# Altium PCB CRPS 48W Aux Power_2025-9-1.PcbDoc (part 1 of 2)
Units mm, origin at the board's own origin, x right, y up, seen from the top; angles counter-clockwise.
Board outline 50 x 33.8 mm, 6 copper layers (TopLayer, Layer2, Layer3, Layer4, Layer5, BottomLayer), stack 1.394 mm thick; 52 components, 33 nets, 144 pads, 115 vias.
Unrouted connection lines stored in the file: 30.
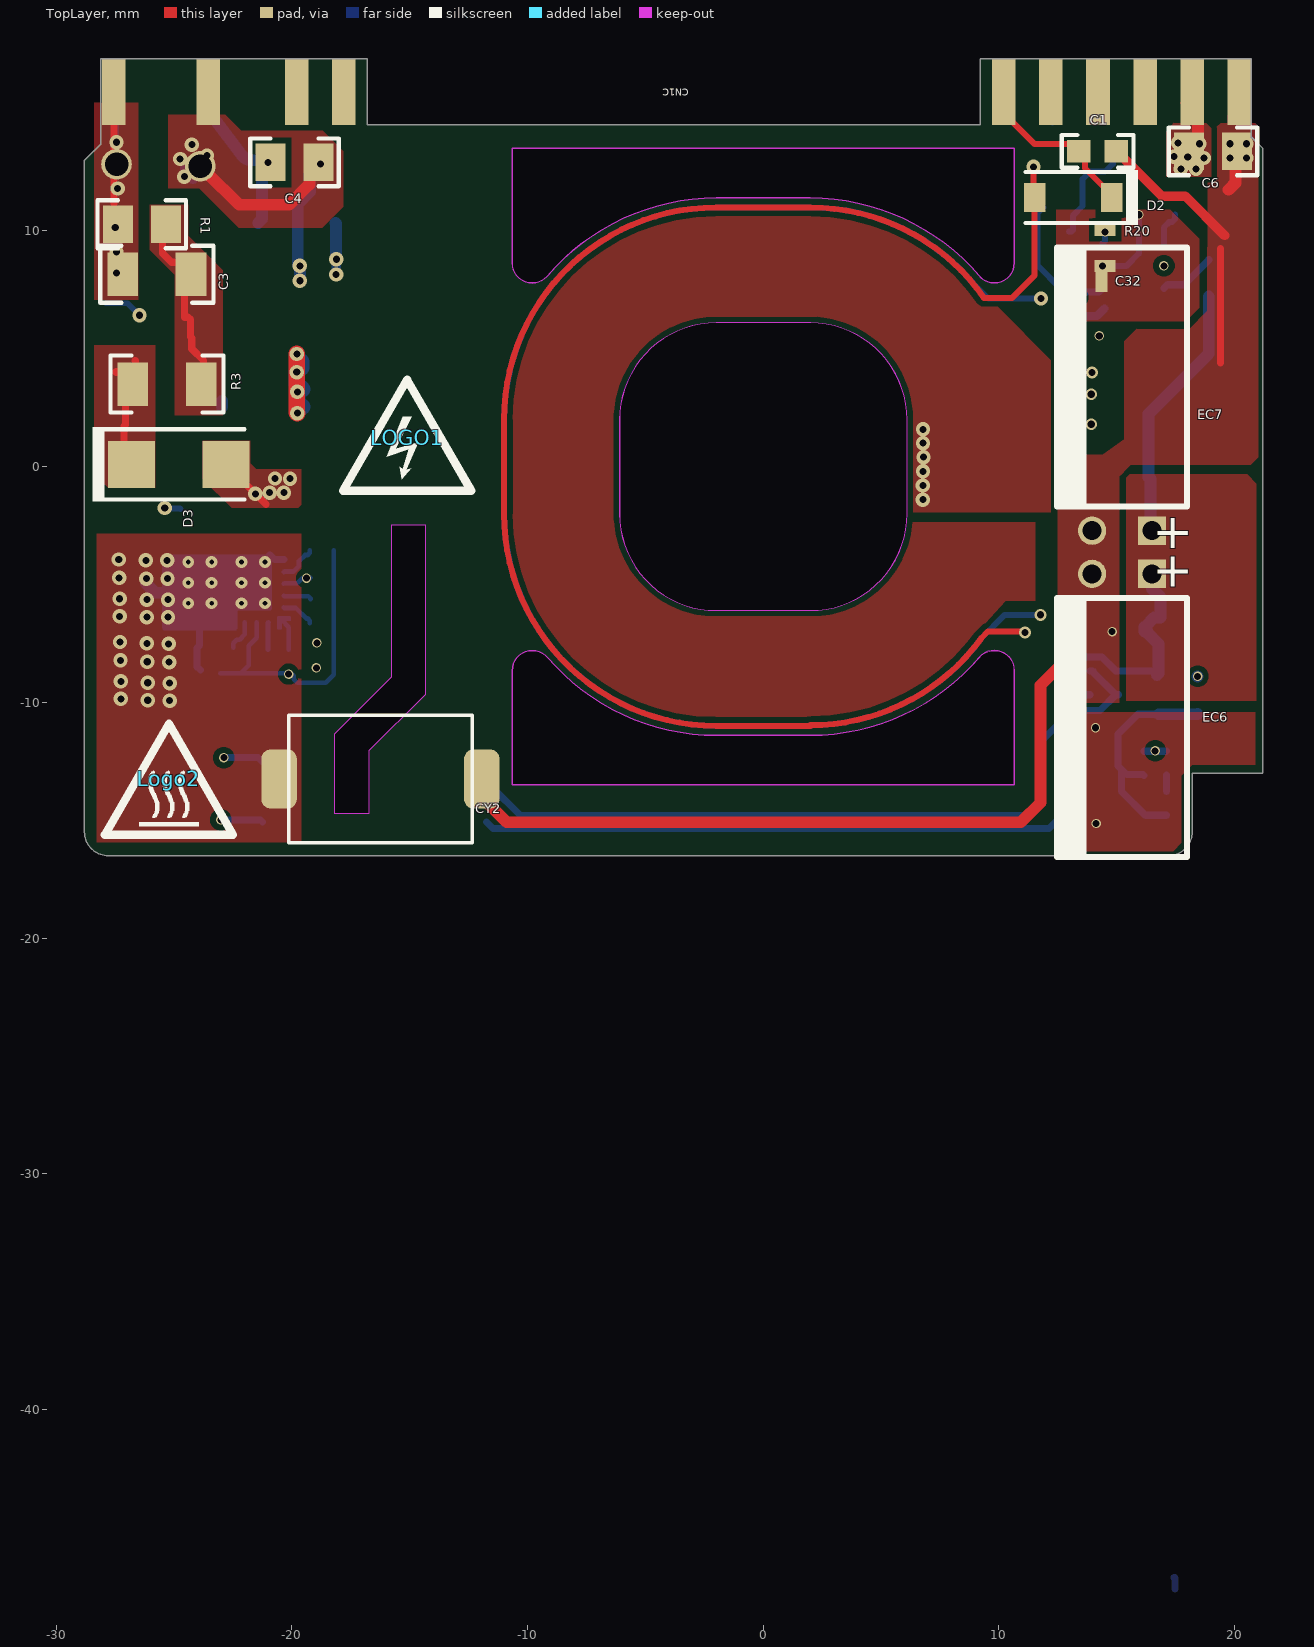
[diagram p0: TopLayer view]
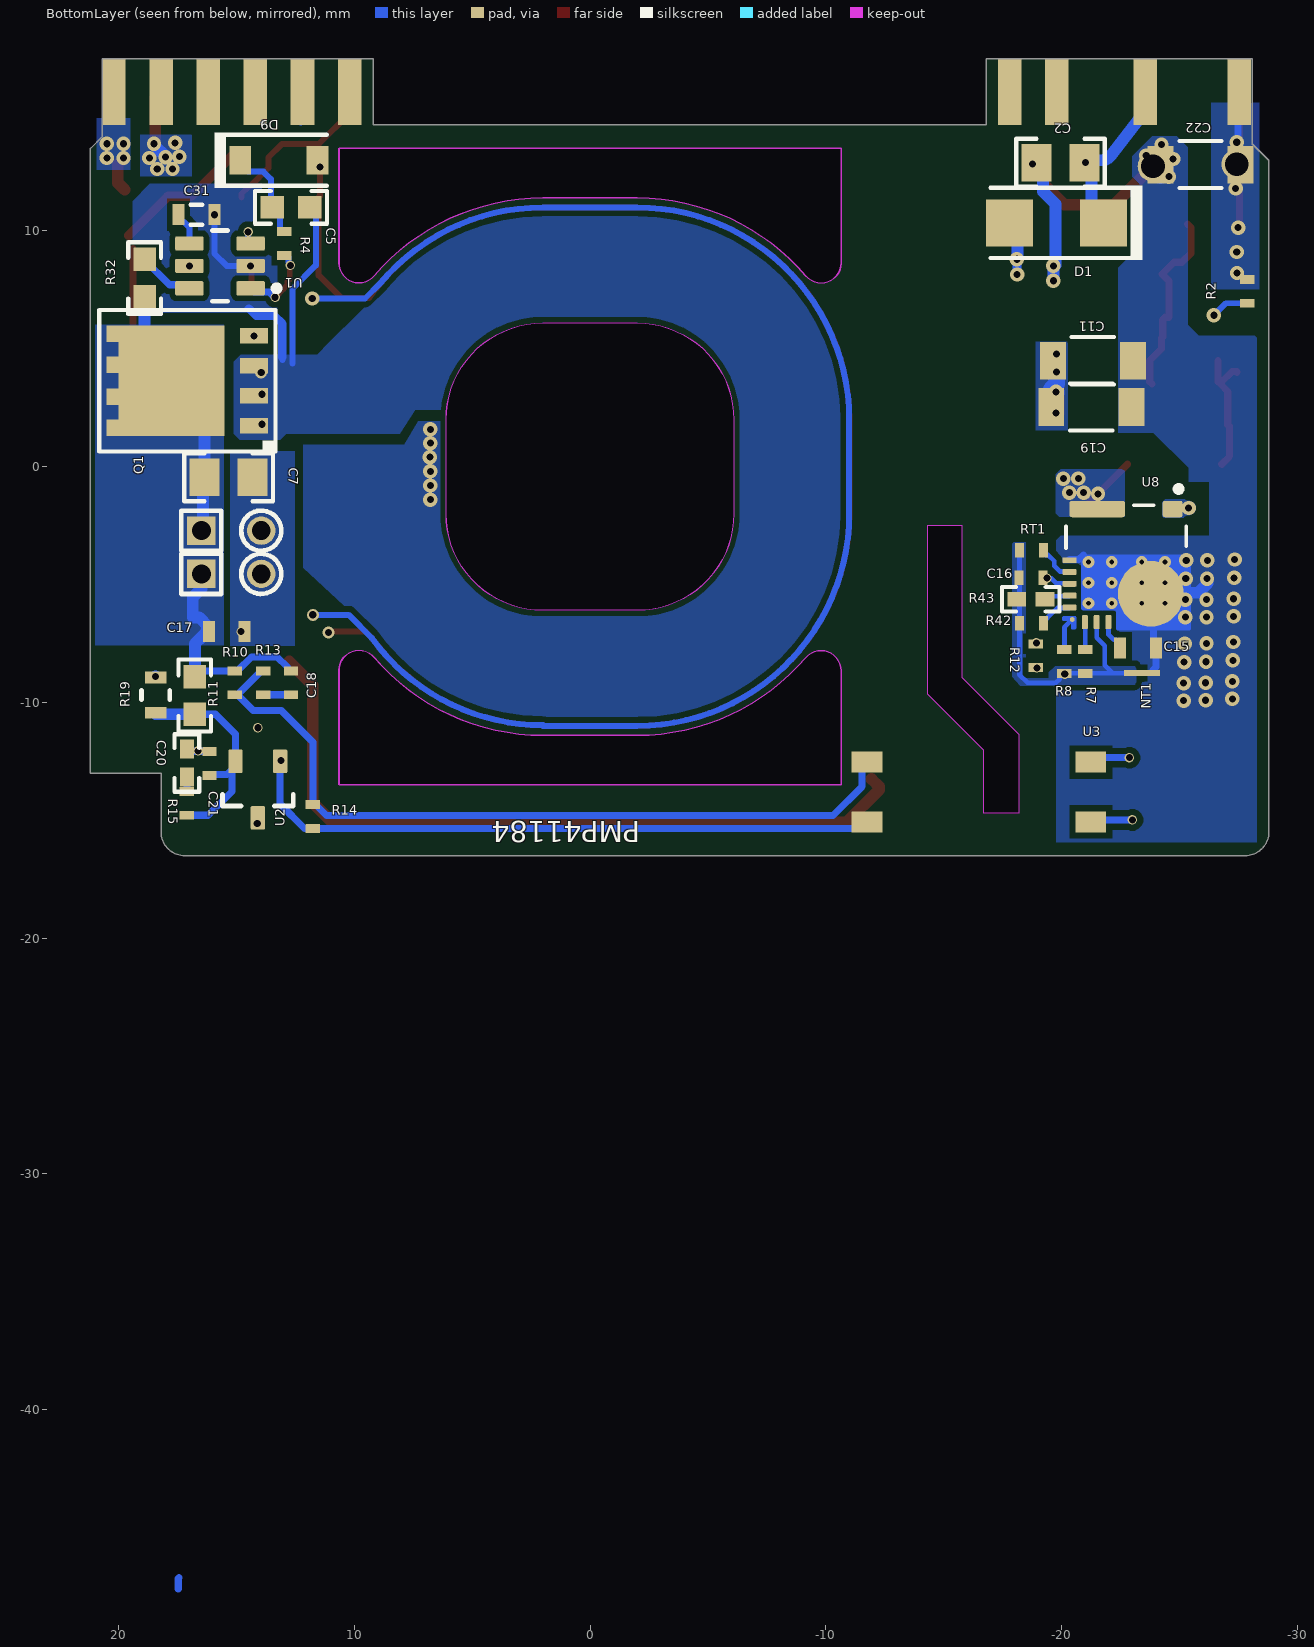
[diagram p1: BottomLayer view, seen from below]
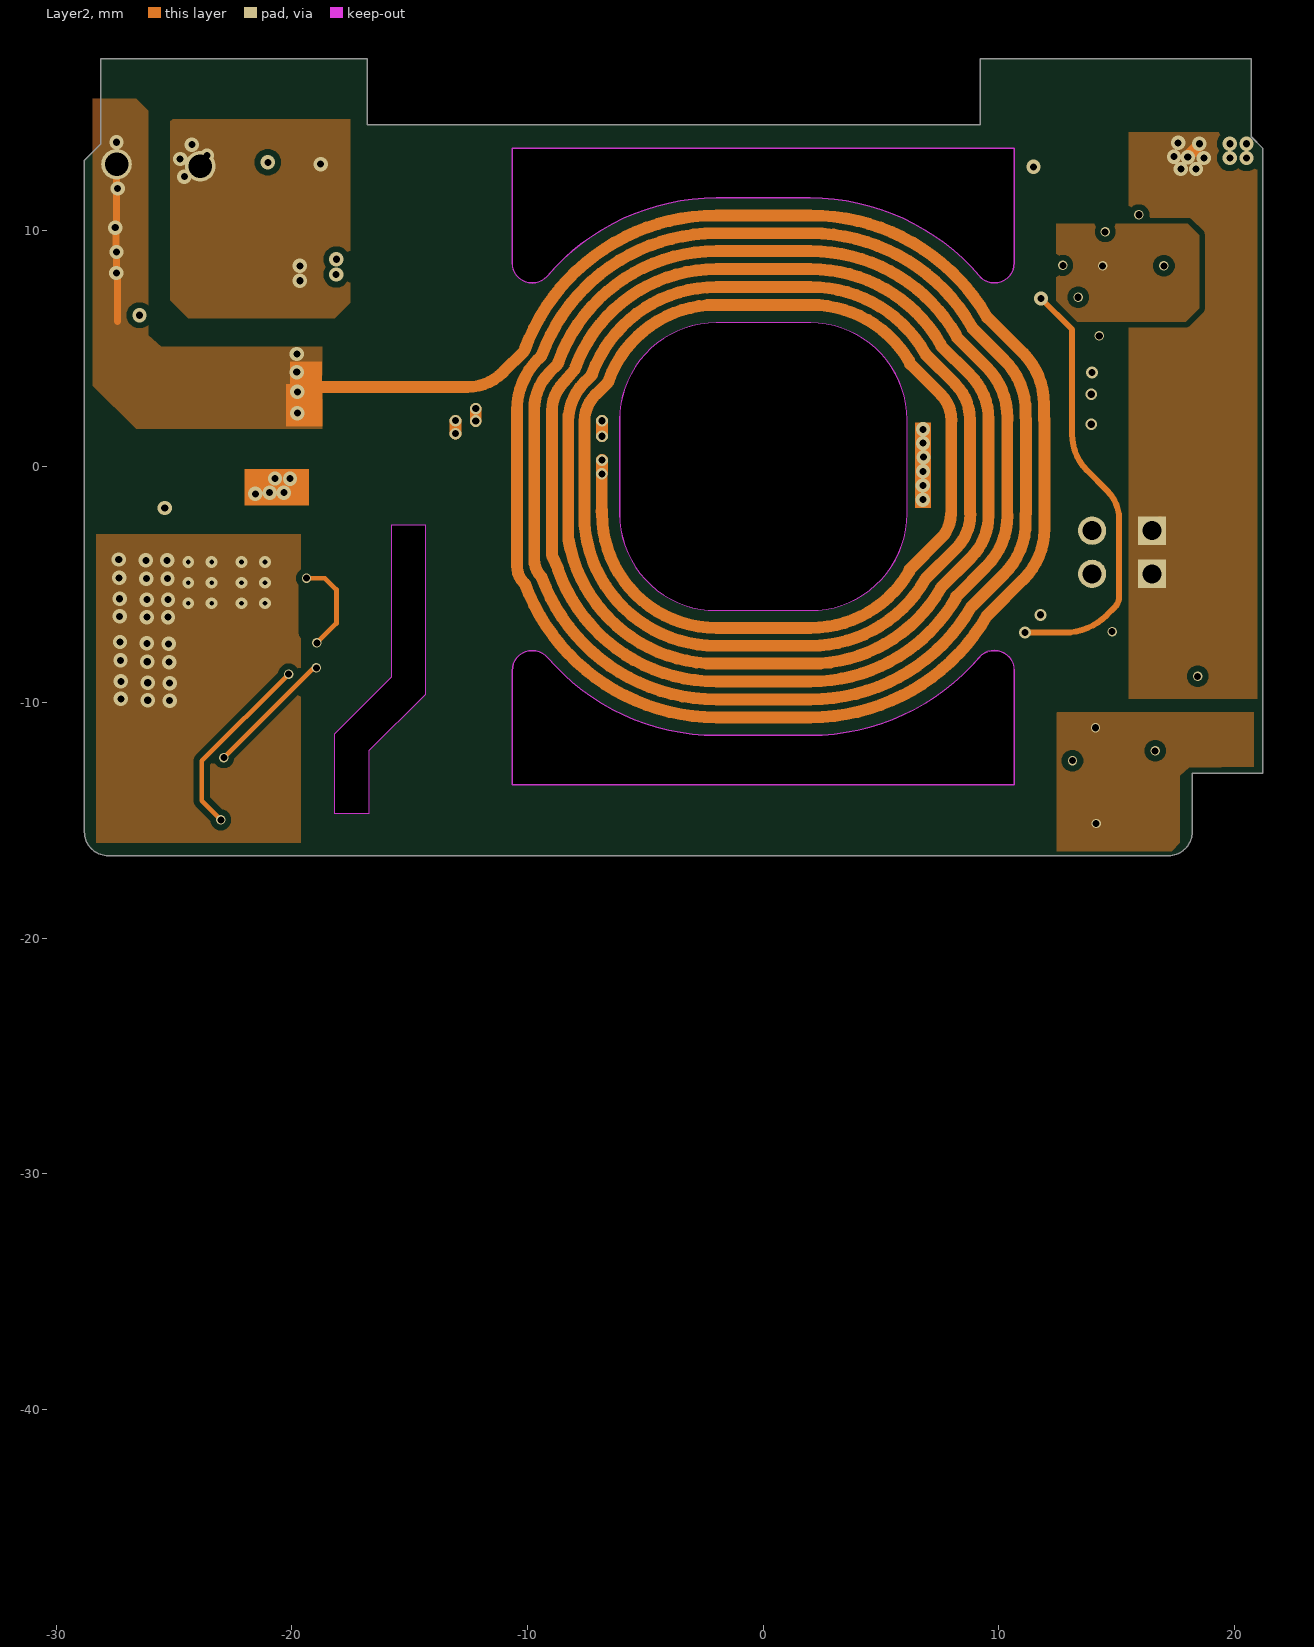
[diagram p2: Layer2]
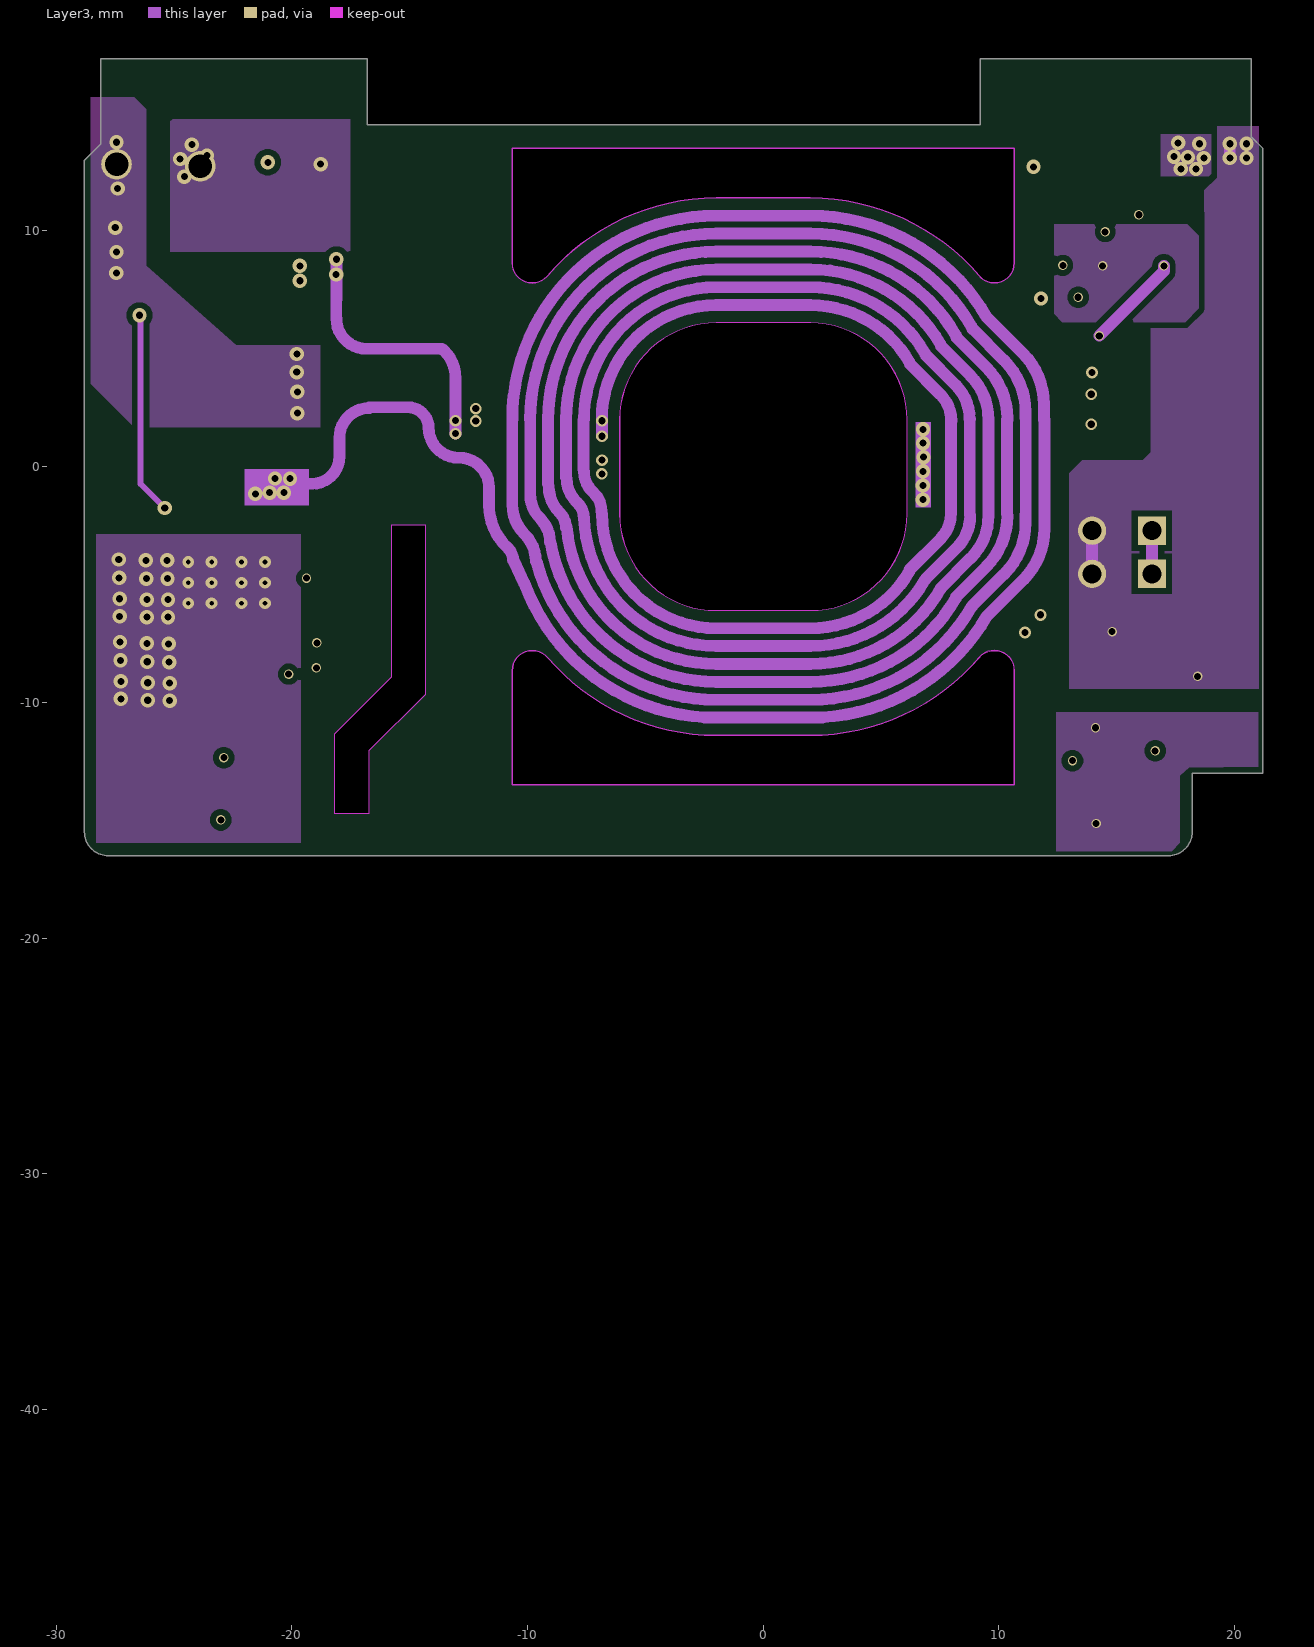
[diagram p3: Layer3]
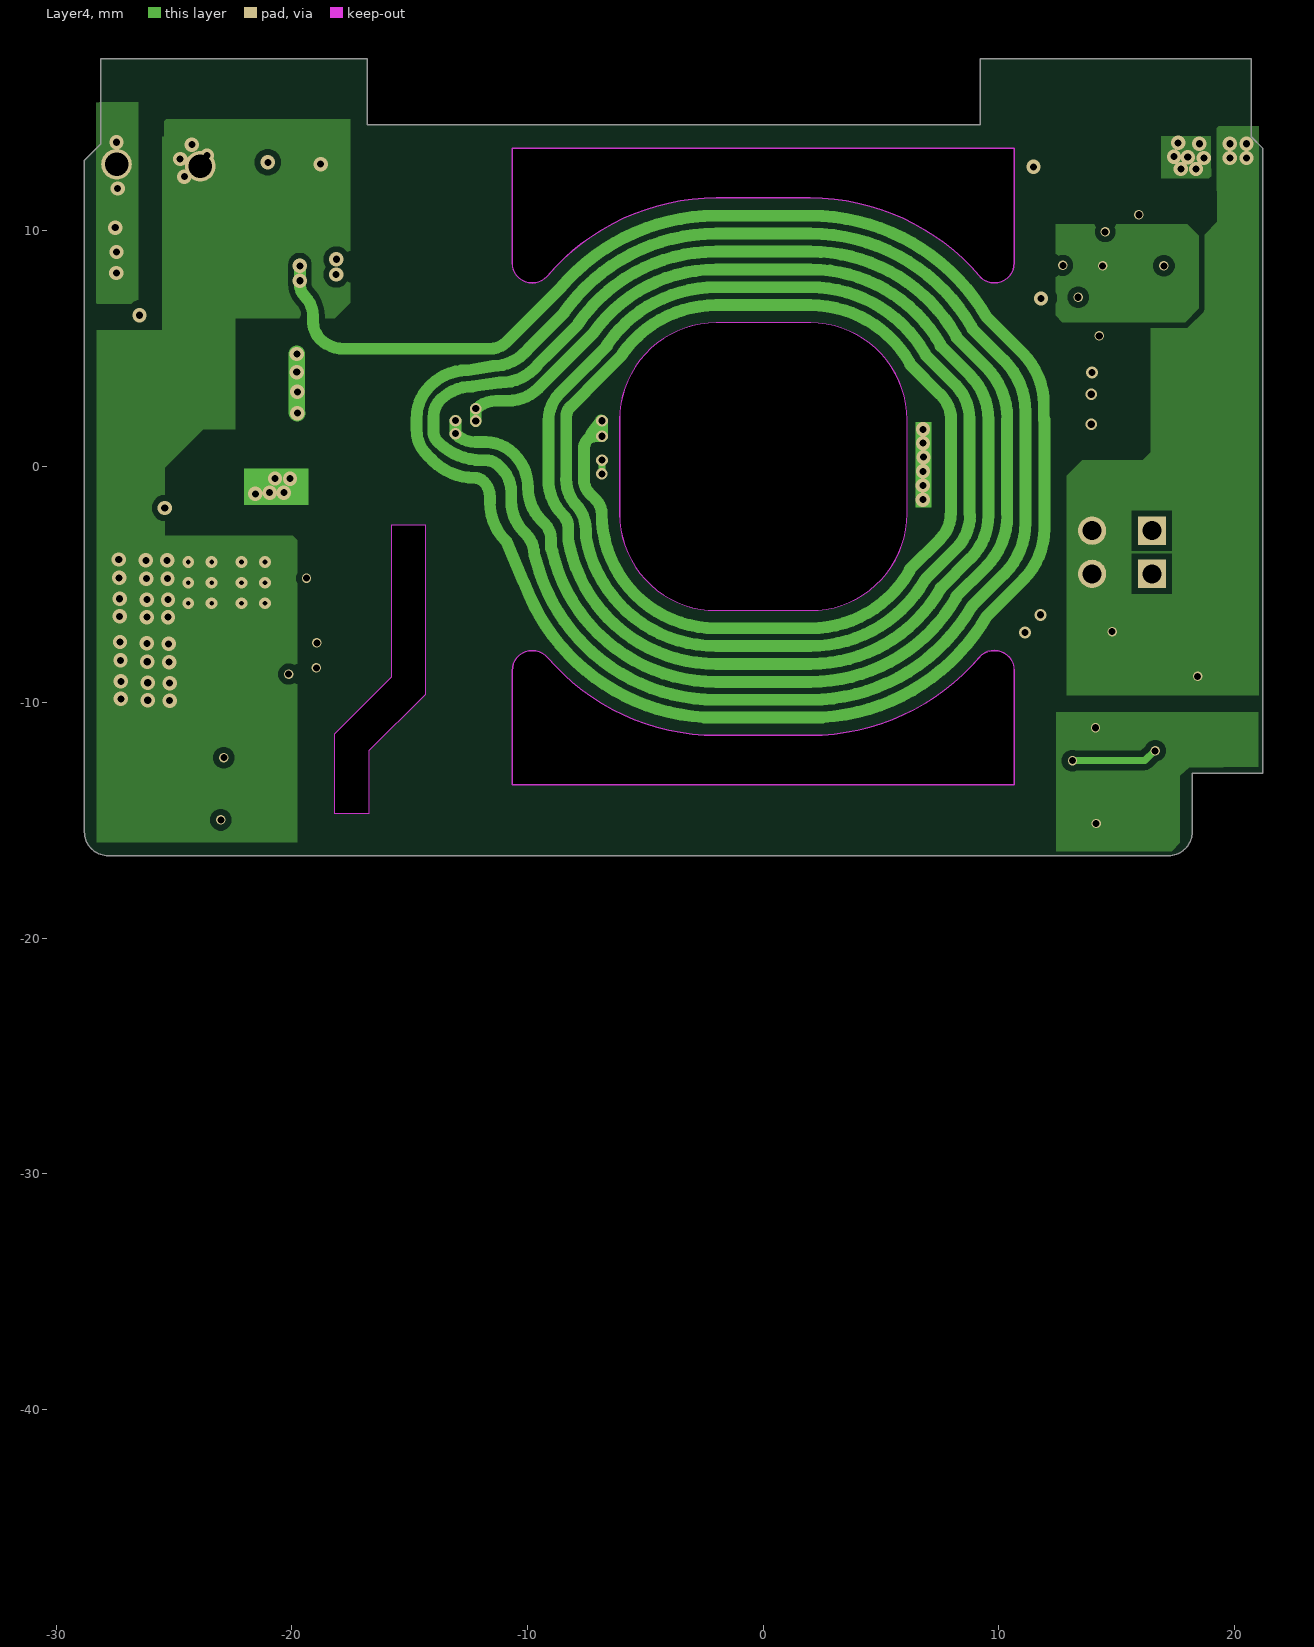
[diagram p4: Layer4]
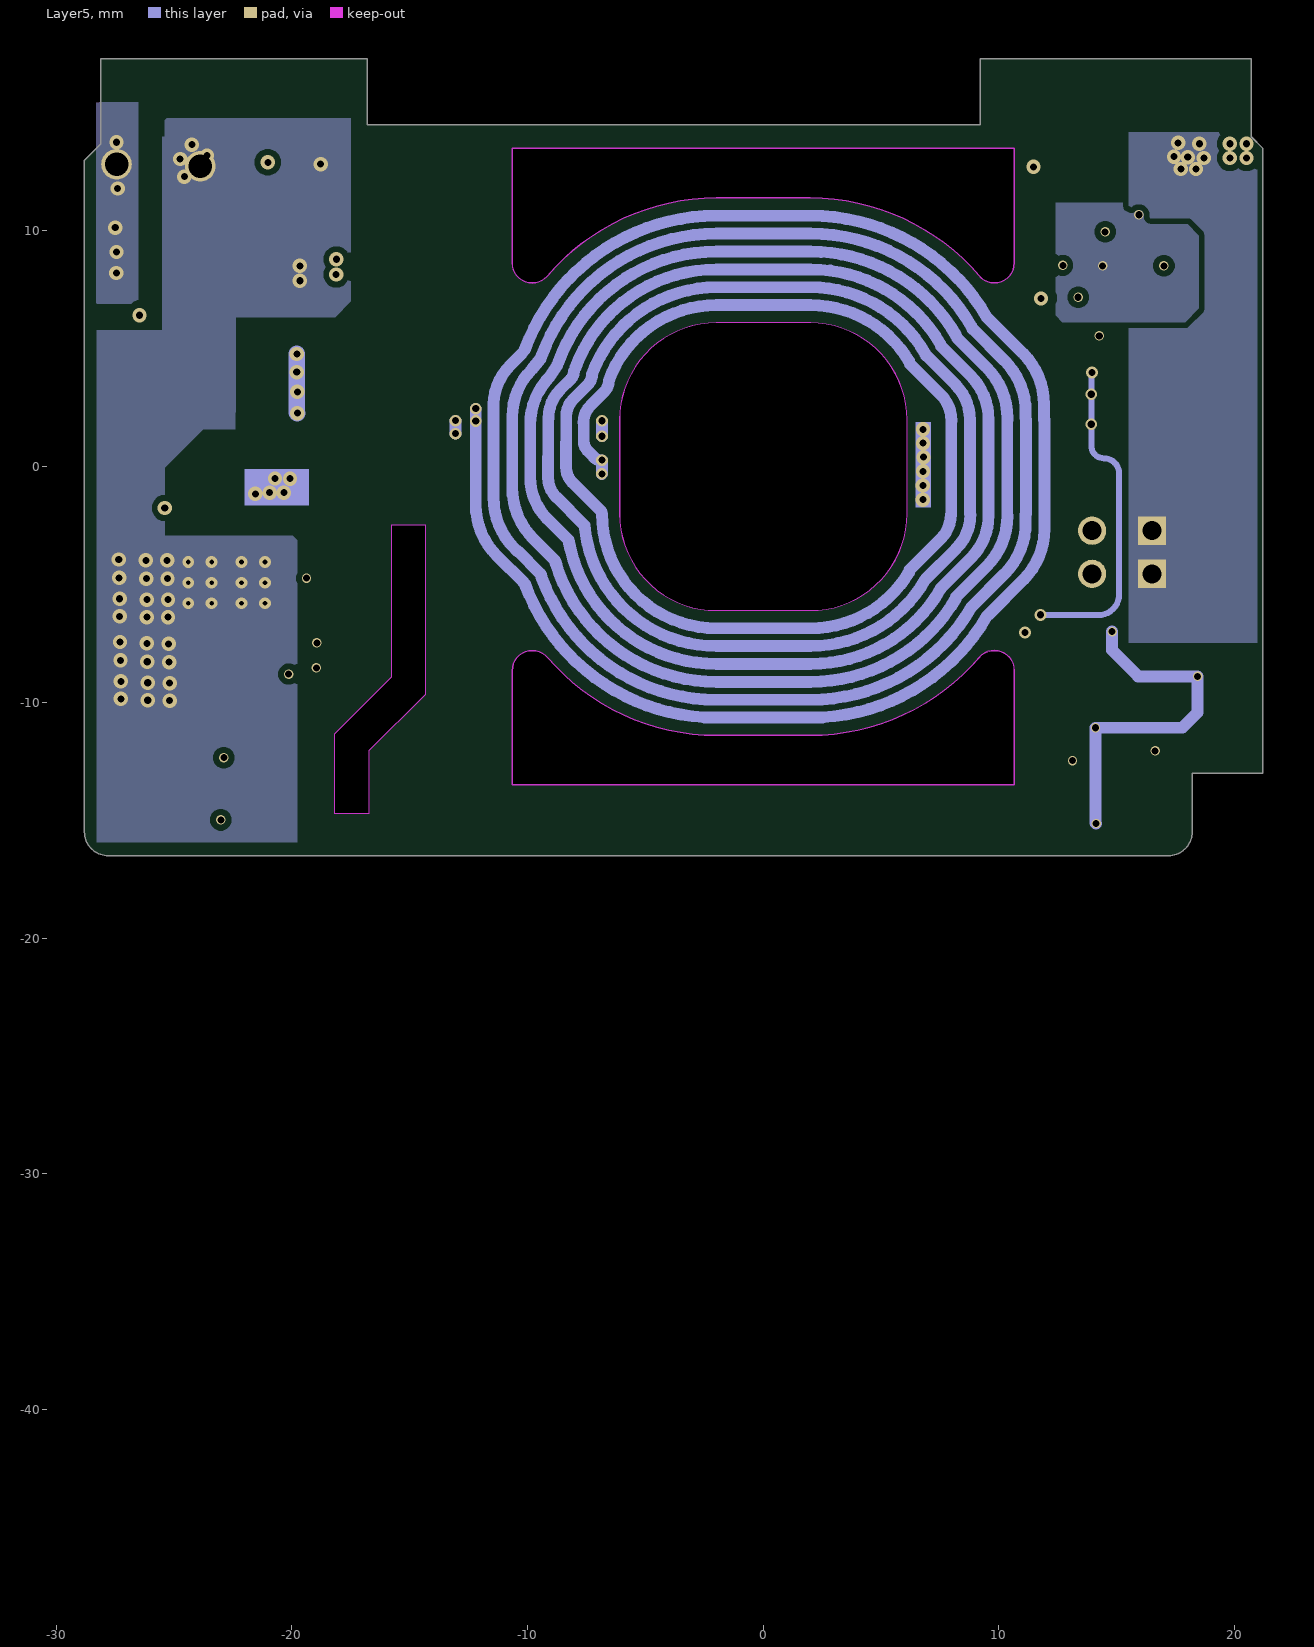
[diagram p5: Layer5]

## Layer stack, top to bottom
Solder Mask Top: solder mask 0.0102, Solder Resist, Dk 3.5
TopLayer: signal copper 0.105
Dielectric 1: dielectric 0.254, FR-4, Dk 4.3
Layer2: signal copper 0.07
Dielectric 2: prepreg 0.0711, PP-006, Dk 4.1
Layer3: signal copper 0.07
Dielectric2: dielectric 0.254, FR-4, Dk 4.3
Layer4: signal copper 0.07
Dielectric 3: prepreg 0.0711, PP-006, Dk 4.1
Layer5: signal copper 0.07
Dielectric3: dielectric 0.254, FR-4, Dk 4.3
BottomLayer: signal copper 0.105
Solder Mask Bottom: solder mask 0.0102, Solder Resist, Dk 3.5

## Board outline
-28.8,-15.5 -28.8,13 -28.1,13.7 -28.1,17.3 -16.8,17.3 -16.8,14.5 9.2,14.5 9.2,17.3 20.7,17.3 20.7,14 21.2,13.5 21.2,-13 18.2,-13 18.2,-15.5 cw(c17.2,-15.5) 17.2,-16.5 -27.8,-16.5 cw(c-27.8,-15.5)
cut-out: -10.65,-13.5 -10.65,-8.65 cw(c-9.8,-8.65) -9.153,-8.099 ccw(c-2,-2) -2,-11.4 2,-11.4 ccw(c2,-2) 9.153,-8.099 cw(c9.8,-8.65) 10.65,-8.65 10.65,-13.5
cut-out: -6.1,-2 ccw(c-2,-2) -2,-6.1 2,-6.1 ccw(c2,-2) 6.1,-2 6.1,2 ccw(c2,2) 2,6.1 -2,6.1 ccw(c-2,2) -6.1,2
cut-out: -10.659,8.64 ccw(c-9.809,8.64) -9.161,8.089 cw(c-2,2) -2,11.4 2,11.4 cw(c2,2) 9.153,8.098 ccw(c9.8,8.65) 10.65,8.65 10.65,13.5 -10.659,13.5
cut-out: -6.096,-2 ccw(c-1.996,-2) -1.996,-6.1 2.004,-6.1 ccw(c2.004,-2) 6.104,-2 6.104,2 ccw(c2.004,2) 2.004,6.1 -1.996,6.1 ccw(c-1.996,2) -6.096,2
cut-out: -10.654,8.64 ccw(c-9.804,8.64) -9.157,8.089 cw(c-1.996,2) -1.996,11.4 2.004,11.4 cw(c2.004,2) 9.157,8.098 ccw(c9.804,8.65) 10.654,8.65 10.654,13.5 -10.654,13.5
cut-out: 10.65,13.5 10.65,8.65 cw(c9.8,8.65) 9.153,8.099 ccw(c2,2) 2,11.4 -2,11.4 ccw(c-2,2) -9.153,8.099 cw(c-9.8,8.65) -10.65,8.65 -10.65,13.5
cut-out: 6.1,2 ccw(c2,2) 2,6.1 -2,6.1 ccw(c-2,2) -6.1,2 -6.1,-2 ccw(c-2,-2) -2,-6.1 2,-6.1 ccw(c2,-2) 6.1,-2
cut-out: 10.659,-8.64 ccw(c9.809,-8.64) 9.161,-8.089 cw(c2,-2) 2,-11.4 -2,-11.4 cw(c-2,-2) -9.153,-8.099 ccw(c-9.8,-8.65) -10.65,-8.65 -10.65,-13.5 10.659,-13.5
cut-out: -15.773,-2.489 -15.773,-8.924 -18.194,-11.345 -18.194,-14.707 -16.713,-14.707 -16.713,-12.04 -14.326,-9.652 -14.326,-2.489

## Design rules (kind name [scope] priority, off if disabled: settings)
Clearance [All] p1: gap=0.25 ignorepadtopadclearanceinfootprint=FALSE except(0: Arc-Hole Track-Hole SMDPad-Hole THPad-Hole Via-Hole Fill-Hole Poly-Hole Region-Hole Text-Hole)
ComponentClearance "ComponentClearance - Default - DEFAULT" [All] p1 off: gap=0.305 collisioncheckmode=3 verticalgap=0.254 showdistances=FALSE
FanoutControl Fanout_SOIC [IsSOIC] p1: bgadir=Out bgaviamode=Centered fanoutstyle=Auto fanoutdirection=Alternating viagrid=0.025 // Fanout_SOIC (Default Rule)
FanoutControl Fanout_Small [(CompPinCount < 5)] p2: bgadir=Out bgaviamode=Centered fanoutstyle=Auto fanoutdirection=OutThenIn viagrid=0.025 // Fanout_Small (Default Rule)
FanoutControl Fanout_BGA [IsBGA] p3: bgadir=Out bgaviamode=Centered fanoutstyle=Auto fanoutdirection=Alternating viagrid=0.025 // Fanout_BGA (Default Rule)
FanoutControl Fanout_LCC [IsLCC] p4: bgadir=Out bgaviamode=Centered fanoutstyle=Auto fanoutdirection=Alternating viagrid=0.025 // Fanout_LCC (Default Rule)
HoleToHoleClearance "HoleToHoleClearance - Default - DEFAULT" [All] p1: gap=0.305 allowstackedmicrovias=TRUE
Length "Default Length" [All] p1 off: maxlimit=1270 minlimit=0
MaxMinImpedance "Default Impedance" [All] p1: minimum=50.00 maximum=150.0
ParallelSegment "Default Parallel Segment Adjasent" [All] p1: limit=25.4 gap=5.08
ParallelSegment "Default Parallel Segment Same Layer" [All] p2: limit=25.4 gap=5.08
PlaneConnect "Default PlaneConnect" [All] p1: planeconnectstyle=Relief reliefexpansion=0.508 reliefentries=0 reliefconductorwidth=0.381 reliefairgap=0.254
PolygonConnect "PolygonConnect - Default SMT" [IsSMTPin] p1: connectstyle=Direct reliefconductorwidth=0.254 reliefentries=4 polygonreliefangle="45 Angle" airgapwidth=0.254
PolygonConnect "PolygonConnect - Default Pad" [All] p2: connectstyle=Direct reliefconductorwidth=0.381 reliefentries=4 polygonreliefangle="45 Angle" airgapwidth=0.254
RoutingLayers "RoutingLayers - Default - DEFAULT" [All] p1: top layer_v5=TRUE mid layer 1_v5=TRUE mid layer 2_v5=TRUE mid layer 3_v5=TRUE mid layer 4_v5=TRUE bottom layer_v5=TRUE
RoutingPriority "RoutingPriority - Default - DEFAULT" [All] p1: routingpriority=3
RoutingTopology "Default Routing Topology" [All] p1: topology=Shortest
RoutingVias "RoutingVias - Default - DEFAULT" [All] p1: holewidth=0.305 width=0.635 viastyle="Through Hole" minholewidth=0.305 minwidth=0.635 maxholewidth=0.305 maxwidth=0.635
SMDToCorner "SMDToCorner - Default - DEFAULT" [All] p1 off: distance=39370
SilkToBoardRegionClearance [All] p1 off:
SilkToSilkClearance [All] p1 off: silktosilkclearance=0.254
SilkToSolderMaskClearance [IsPad] p1 off: minsilkscreentomaskgap=0.254 clearancetoexposedcopper=TRUE
SolderMaskExpansion [All] p1: expansion=0.102 istentingtop=FALSE
UnpouredPolygon [All] p1: allowunpoured=TRUE
Width "Width - Net - $$$25405" [InNet('$$$25405')] p1: maxlimit=2 minlimit=0.1 preferedwidth=0.25
Width "Default Width" [All] p2: maxlimit=2 minlimit=0.1 preferedwidth=0.25
16 further rules are at their usual default settings.

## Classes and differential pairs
net class "Switch Node": VSW
net class SGND: +12V SGND
net class PGND: PGND
net class "High Voltage": NetR2_1 Vbus

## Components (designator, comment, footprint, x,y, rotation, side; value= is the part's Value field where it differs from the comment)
C1 "GRM188R6YA106MA73" 0603 14.184,13.377 r0 top value=10uF
C2 "TMK212BBJ106KG-T" 0805_HV -19.961,12.9 r0 bottom value=10uF
C3 "GRM31BR72J102KW01L" 1206 -25.73,8.164 r180 top value=1000pF
C4 "TMK212BBJ106KG-T" 0805_HV -19.888,12.912 r0 top value=10uF
C5 "GRM188R6YA225KA12D" 0603 12.685,11 r180 bottom value=2.2uF
C6 "TMK212BBJ106KG-T" 0805_HV 19.081,13.377 r0 top value=10uF
C7 "TMK212BBJ106KG-T" 0805_HV 15.336,-0.452 r180 bottom value=10uF
C11 "C3216X7T2W104M160AA" 1206_180 -21.336,4.496 r180 bottom value=0.1uF
C15 "GRM188R61E106KA73D" 0603S -23.255,-7.688 r180 bottom value=10uF
C16 "GRM155R71H331KA01D" 0402S -18.702,-4.716 r0 bottom value=330pF
C17 "C1608X7R1E105K080AB" 0603S 15.413,-7 r0 bottom value=1uF
C18 "GRM155R71H183KA12D" 0402S 12.685,-9.168 r270 bottom value=0.018uF
C19 "C3216X7T2W104M160AA" 1206_180 -21.267,2.535 r180 bottom value=0.1uF
C20 "C1005X7R1H683K050BB" 0402 17.103,-12.573 r90 bottom value=0.068uF
C21 "885012205055" 0402S 16.144,-12.592 r90 bottom value=100pF
C22 "C3216X7T2W104M160AA" 1206_180 -25.9,12.813 r0 bottom value=0.1uF
C31 "CGA3E1X7R1E105K080AC" 0603S 16.7,10.69 r180 bottom value=1uF
C32 "C1608X7R1E105K080AB" 0603S 13.596,7.861 r0 top value=1uF
CN1C "SIP/20P/D....ABBBB" SIP$2F$2.54_2X09P_D_PPAAAABBBBBB -23.55,15.9 r0 top
CY2 "" "CY SMD" -16.242,-13.25 r180 top value=470pF
D1 "ES2DA-13-F" SMA -19.79,10.346 r0 bottom value=200V
D2 "BAV21W-7-F" SOD-123 13.155,11.417 r180 top value=200V
D3 "MRA4007T3G" SMA -24.8,0.1 r0 top value=1000V
D9 "BAV21W-7-F" SOD-123 13.2,13 r180 bottom value=200V
EC6 "ECAP_LAYDOWN" CE05.5P254L11 16.49,-4.548 r180 top locked value=470uF
EC7 "ECAP_LAYDOWN" CE05.5P254L11 16.49,-2.715 r180 top locked value=470uF
LOGO1 "DANGER HIGH VOLTAGE" IEC_HighVoltage_Small -15.113,1.219 r0 top
Logo2 "CAUTION HOT SURFACE" IEC_HotSurface_Small -25.214,-13.25 r0 top
NT1 "Net-Tie" Net-Tie_10milWide_30milLong -23.419,-8.758 r0 bottom net-tie
Q1 "ISC030N10NM6" PG-TDSON-8 17.08,3.648 r0 bottom value=150V
R1 "CRCW0805470KJNEA" 0805_HV -26.365,10.287 r180 top value=470k
R2 "CRCW04021R00JNED" 0402S -27.889,7.442 r90 bottom value=1.0
R3 "RC1206FR-0730RL" 1206 -25.298,3.505 r0 top value=30.0
R4 "CRCW04023R30JNED" 0402S 12.979,9.47 r270 bottom value=3.3
R7 "CRCW040214K3FKED" 0402S -21.016,-8.272 r90 bottom value=14.3k
R8 "CRCW040236K5FKED" 0402S -20.127,-8.272 r90 bottom value=36.5k
R10 "CRCW04023K01FKED" 0402S 15.066,-9.168 r90 bottom value=3.01k
R11 "RT0603BRD0738K8L" 0603 16.766,-9.71 r90 bottom value=38.8k
R12 "CRCW04021R10FKED" 0402S -18.912,-8.022 r270 bottom value=1.10
R13 "CRCW0402150RFKED" 0402S 13.862,-9.168 r270 bottom value=150
R14 "CRCW040215K0FKED" 0402S 11.762,-14.847 r90 bottom value=15.0k
R15 "RC0402FR-074K7L" 0402S 17.103,-14.281 r270 bottom value=4.70k
R19 "TNPW060310K0BEEA" TNPW0603 18.428,-9.694 r270 bottom value=10.0k
R20 "RC0603FR-0756K2L" 0603S 14.507,9.282 r90 top value=56.2k
R32 "RC0603FR-07300RL" 0603 18.9,7.999 r90 bottom value=300
R42 "CRCW040275K0FKED" 0402S -18.728,-6.645 r180 bottom value=75.0k
R43 "CRCW04025K23FKED" 0402 -18.702,-5.627 r180 bottom value=5.23k
RT1 "NCP15WF104F03RC" 0402S -18.728,-3.544 r180 bottom value=100k
U1 "MP6908GJ-Z" FP-MP6908GJ-Z_TSOT23-6-MFG 15.7,8.52 r0 bottom
U2 "ATL431AIDBZR" DBZ0003A_N 14.096,-13.7 r270 bottom
U3 "VOL618A-2T" SOP254P1020X230-4 -16.5,-13.8 r180 bottom
U8 "UCG28682" REZ0012A-MFG -22.744,-4.195 r270 bottom

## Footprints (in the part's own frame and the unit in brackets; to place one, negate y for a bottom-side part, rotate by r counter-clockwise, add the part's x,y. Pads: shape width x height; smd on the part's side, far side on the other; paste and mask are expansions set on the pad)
0402 [mm] "0402 from SM-752 data"
  rect 0.8x0.6 smd: 1(-0.6,0) 2(0.6,0)
  silkscreen extent -1.22,-0.52 1.22,0.52, body extent -0.55,-0.3 0.55,0.3, height 0.6
0402S [mil] "Based on C0402S footprint from PADS legacy"
  rect 15x24 smd: 1(-20,0) 2(20,0)
  body extent -22,-12 22,12, height 24
0603 [mm] "0603 from SM-752 data"
  rect 1x0.95 smd: 1(-0.8,0) 2(0.8,0)
  silkscreen extent -1.52,-0.69 1.52,0.69, body extent -0.87,-0.47 0.87,0.47, height 1
0603S [mil]
  rect 20x35 smd: 1(-30,0) 2(30,0)
  body extent -34,-19 34,19, height 39
0805_HV [mil] "0805 with 30mil clearance between pads"
  rect 50x63 smd: 1(-40,0) 2(40,0)
  silkscreen extent -74,-40 74,40, body extent -43,-29 43,29, height 57
1206 [mm] "1206 from SM-752 data"
  rect 1.3x1.85 smd: 1(-1.45,0) 2(1.45,0)
  silkscreen extent -2.4,-1.21 2.4,1.21, body extent -1.7,-0.9 1.7,0.9, height 1.35
1206_180 [mm] "1206_180"
  rect 1.1x1.6 smd: 1(-1.7,0) 2(1.7,0)
  silkscreen extent -0.9,-1 0.9,1, body extent -1.75,-0.95 1.75,0.95, height 1.8
CE05.5P254L11 [mm]
  rect 1.2x1.2 hole 0.8: 1(0,0)
  round 1.2 hole 0.8: 2(2.54,0)
  silkscreen extent -1.48,1.02 4.02,12.02, body extent -1.23,1.05 3.77,11.05, height 5
"CY SMD" [mm]
  rrect50% 1.5x2.5 smd: 1(-4.3,0) 2(4.3,0)
  silkscreen extent -3.9,-2.71 3.9,2.7, body extent -3.9,-2.7 3.9,2.7, height 2.5
DBZ0003A_N [mm] "SOT23, 3-Leads, Body 2.9x1.3mm, Pitch 0.95mm, Lead Span 2.4mm, IPC Medium Density"
  rrect17% 1x0.6 smd: 1(-1.2,0.95) 2(-1.2,-0.95) 3(1.2,0)
  silkscreen extent 0.2,-1.5 0.7,1.5, body extent -1.26,-1.46 1.26,1.46, height 0.98
FP-MP6908GJ-Z_TSOT23-6-MFG [mm]
  rrect17% 1.2x0.6 smd paste+0 mask+0: 1(-1.3,0.95) 2(-1.3,0) 3(-1.3,-0.95) 4(1.3,-0.95) 5(1.3,0) 6(1.3,0.95)
  silkscreen extent -2.52,-1.5 0.33,1.5, body extent -1.4,-1.45 1.4,1.45, height 1
IEC_HighVoltage_Small [mm]
  silkscreen extent -2.72,-2.24 2.72,2.47
IEC_HotSurface_Small [mm]
  silkscreen extent -2.72,-2.36 2.72,2.35
Net-Tie_10milWide_30milLong [mil] "10mil net tie, no solder mask opening, no solder paste"
  rect 30x10 smd paste-5 mask-5: 1(-15,0) 2(15,0)
PG-TDSON-8 [mm] "Infineon recommended land pattern"
  rect 1.2x0.65 smd: 1(-2.825,1.905) 2(-2.825,0.635) 3(-2.825,-0.635) 4(-2.825,-1.905)
  rect 0.5x0.7 smd: 5(3.175,-2) 6(3.175,-0.675) 7(3.175,0.675) 8(3.175,2)
  rect 4.5x4.7 smd paste-2.25: 9(0.675,0)
  silkscreen extent -3.74,-3 3.74,3, body extent -3.17,-2.89 3.17,2.9, height 1.1
REZ0012A-MFG [mm]
  rrect29% 0.7x0.85 smd paste-1000 mask-1000: 1(-2.4,1.975)
  rrect29% 0.7x2.35 smd paste-1000 mask-1000: 2(-2.4,-1.225)
  rrect40% 0.25x0.6 smd paste+0 mask+0: 3(-0.225,-2.4) 4(0.275,-2.4) 5(0.775,-2.4) 6(1.275,-2.4) 7(1.775,-2.4)
  round 0.203 smd paste+0 mask+0: 8(2.288,-2.288)
  rrect40% 0.6x0.25 smd paste+0 mask+0: 9(2.4,-1.75) 10(2.4,-1.25) 11(2.4,-0.75)
  round 2.788 smd paste-1000 mask-1000: 12(1.199,1.048)
  TopLayer region: -0.45,2.65 -0.437,2.7 -0.4,2.737 -0.35,2.75 -0.35,2.75 2.648,2.75 2.698,2.737 2.735,2.7 2.748,2.65 2.748,2.65 2.748,-0.325 2.735,-0.375 2.698,-0.412 2.648,-0.425 2.648,-0.425 1.95,-0.425 1.931,-0.429 1.915,-0.44 1.904,-0.456 1.9,-0.475 1.9,-0.475 1.9,-1.8 1.887,-1.85 1.85,-1.887 1.8,-1.9 1.8,-1.9 -0.35,-1.9 -0.4,-1.887 -0.437,-1.85 -0.45,-1.8 -0.45,-1.8
  TopLayer region: 2.2,-2.7 2.175,-2.693 2.157,-2.675 2.15,-2.65 2.15,-2.65 2.15,-2.175 2.154,-2.156 2.165,-2.14 2.181,-2.129 2.2,-2.125 2.2,-2.125 2.65,-2.125 2.669,-2.129 2.685,-2.14 2.696,-2.156 2.7,-2.175 2.7,-2.175 2.7,-2.275 2.693,-2.3 2.675,-2.318 2.65,-2.325 2.65,-2.325 2.45,-2.325 2.412,-2.333 2.379,-2.354 2.358,-2.387 2.35,-2.425 2.35,-2.425 2.35,-2.65 2.343,-2.675 2.325,-2.693 2.3,-2.7 2.3,-2.7
  silkscreen extent -3.37,-2.55 -0.72,2.55, body extent -2.5,-2.5 2.5,2.5, height 1
SIP$2F$2.54_2X09P_D_PPAAAABBBBBB [mm]
  rect 1x2.8 smd: 1(-4,0) 3(0,0) 5(3.75,0) 7(5.75,0) 9(33.75,0) 11(35.75,0) 13(37.75,0) 15(39.75,0) 17(41.75,0) 19(43.75,0)
  rect 1x2.8 smd far side: 2(-4,0) 4(0,0) 6(3.75,0) 8(5.75,0) 10(33.75,0) 12(35.75,0) 14(37.75,0) 16(39.75,0) 18(41.75,0) 20(43.75,0)
SMA [mm] "Molded Diode, 2-Leads, Body 4.3x2.6mm, IPC Medium Density, based on OnSemi component dimensions and land pattern"
  rect 2x2 smd: 1(-2,0) 2(2,0)
  silkscreen extent -3.66,-1.57 2.79,1.57, body extent -2.6,-1.3 2.6,1.3, height 2.42
SOD-123 [mm] "On Semi recommended land pattern"
  rect 0.915x1.22 smd: 1(-1.638,0) 2(1.638,0)
  silkscreen extent -2.74,-1.17 2.03,1.17, body extent -1.93,-0.9 1.93,0.9, height 1.35
SOP254P1020X230-4 [mm] "VISHAY"
  rect 1.3x0.9 smd: 1(-4.75,1.27) 2(-4.75,-1.27) 3(4.75,-1.27) 4(4.75,1.27)
  body extent -3.85,-2.05 3.85,2.05, height 2.02
TNPW0603 [mm] "Vishay"
  rect 0.5x0.9 smd: 1(-0.75,0) 2(0.75,0)
  silkscreen extent -0.2,-0.6 0.2,0.6, body extent -0.85,-0.47 0.85,0.47, height 0.55

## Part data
C1: library part CMP-0007355-5, "CAP, CERM, 10 uF, 35 V, +/- 20%, X5R, 0603", Cap_Case=0603, Manufacturer=Nichicon, TempCo=X5R, Tolerance_%=20%, Value1=Unknown, Value2=35V, ValueDisplayed=10uF
C2 C4 C6 C7: library part CMP-0008414-2, "CAP, CERM, 10 uF, 25 V, +/- 10%, X5R, 0805", Cap_Case=0805, Manufacturer="Taiyo Yuden", Supplier Part Number 1=587-2985-1-ND, TempCo=X5R, Tolerance_%=10%, Value1=Unknown, Value2=25V, ValueDisplayed=10uF
C3: library part CMP-0008909-2, "CAP, CERM, 1000 pF, 630 V, +/- 10%, X7R, 1206", Cap_Case=1206, Manufacturer=MuRata, Supplier Part Number 1=490-3506-1-ND, TempCo=X7R, Tolerance_%=10%, Value1=Unknown, Value2=630V, ValueDisplayed=1000pF
C5: library part CMP-0007356-4, "CAP, CERM, 2.2 uF, 35 V, +/- 10%, X5R, 0603", Cap_Case=0603, Manufacturer=MuRata, Supplier Part Number 1=490-7204-6-ND, TempCo=X5R, Tolerance_%=10%, Value1=Unknown, Value2=35V, ValueDisplayed=2.2uF
C11 C19 C22: library part CMP-0008729-1, "CAP, CERM, 0.1 uF, 450 V, +/- 20%, X7T, 1206", Cap_Case=1206, Manufacturer=TDK, Supplier Part Number 1=445-14838-1-ND, TempCo=X7T, Tolerance_%=20%, Value1=Unknown, Value2=450V, ValueDisplayed=0.1uF
C15: library part CMP-0860569-1, "CAP, CERM, 10 µF, 25 V,+/- 10%, X5R, 0603", Cap_Case=0603, Manufacturer=MuRata, TempCo=X5R, Tolerance_%=10%, Value2=25V, ValueDisplayed=10µF
C16: library part CMP-0006687-2, "CAP, CERM, 330 pF, 50 V, +/- 10%, X7R, 0402", Cap_Case=0402, Manufacturer=MuRata, Supplier Part Number 1=490-3247-1-ND, TempCo=X7R, Tolerance_%=10%, Value1=Unknown, Value2=50V, ValueDisplayed=330pF
C17: library part CMP-0007040-4, "CAP, CERM, 1 µF, 25 V, +/- 10%, X7R, 0603", Cap_Case=0603, Manufacturer=TDK, Supplier Part Number 1=445-5956-1-ND, TempCo=X7R, Tolerance_%=10%, Value1=Unknown, Value2=25V, ValueDisplayed=1uF
C18: library part CMP-0006681-2, "CAP, CERM, 0.018 uF, 50 V, +/- 10%, X7R, 0402", Cap_Case=0402, Manufacturer=MuRata, Supplier Part Number 1=GRM155R71H183KA12D-ND, TempCo=X7R, Tolerance_%=10%, Value1=Unknown, Value2=50V, ValueDisplayed=0.018uF
C20: library part CMP-0006299-1, "CAP, CERM, 0.068 uF, 50 V, +/- 10%, X7R, 0402", Cap_Case=0402, Manufacturer=TDK, Supplier Part Number 1=445-5930-1-ND, TempCo=X7R, Tolerance_%=10%, Value1="0.05606 ohm", Value2=50V, ValueDisplayed=0.068uF
C21: library part CMP-0006230-2, "CAP, CERM, 100 pF, 50 V, +/- 10%, X7R, 0402", Cap_Case=0402, Manufacturer="Wurth Elektronik", Supplier Part Number 1=732-7550-1-ND, TempCo=X7R, Tolerance_%=10%, Value1=Unknown, Value2=50V, ValueDisplayed=100pF
C31: library part CMP-0076705-1, "CAP, CERM, 1 µF, 25 V,+/- 10%, X7R, AEC-Q200 Grade 1, 0603", Cap_Case=1.6x0.8x0.8mm, Manufacturer=TDK, Supplier Part Number 1=445-6931-1-ND, TempCo=X7R, Tolerance_%=10%, Value2=25V, ValueDisplayed=1µF
C32: library part CMP-0007040-4, "CAP, CERM, 1 uF, 25 V, +/- 10%, X7R, 0603", Cap_Case=0603, Manufacturer=TDK, Supplier Part Number 1=445-5956-1-ND, TempCo=X7R, Tolerance_%=10%, Value1=Unknown, Value2=25V, ValueDisplayed=1uF
CY2: library part "220pF Y Cap", "470pF Y1 Cap", PartNumber=TMY1471K
D1: library part CMP-0076892-1, "Diode, Superfast Rectifier, 200 V, 2 A, SMA", Manufacturer="Diodes Inc.", Supplier Part Number 1=ES2DA-FDICT-ND, Value1=2A, Value2=0.92V
D2 D9: library part CMP-0029031-2, "Diode, Switching, 200 V, 0.2 A, SOD-123", Manufacturer="Diodes Inc.", Value1=0.2A, Value2=1.25V
D3: library part CMP-0077082-2, "Diode, Standard Recovery Rectifier, 1000 V, 1 A, AEC-Q101, SMA", Manufacturer="ON Semiconductor", Value1=1A, Value2=1.1V
EC6 EC7: "25V/470uF D5.5*11mm", Manufacturer=Yongming, PartNumber=NPXC1001E471MJTM, Voltage=25V
LOGO1: library part CMP-0074835-1, "IEC 61010-1 High Voltage Warning"
Logo2: library part CMP-0074837-2, "IEC 61010-1 Hot Surface Warning", Manufacturer="Texas Instruments"
NT1: library part CMP-0078142-6, "Single point connection between nets.", Manufacturer=N/A
Q1: library part CMP-0001046-2, "MOSFET, N-CH, 150 V, 87 A, PG-TDSON-8", Alternate Manufacturer=None, Manufacturer="Infineon Technologies", PartNumber=BSC093N15NS5ATMA1, Supplier Part Number 1=BSC093N15NS5ATMA1CT-ND, Value2="33 nC"
R1: library part CMP-0020554-3, "RES, 470 k, 5%, 0.125 W, AEC-Q200 Grade 0, 0805", Manufacturer=Vishay-Dale, Power_W=125mW, Supplier Part Number 1=541-470KACT-ND, TempCo="200 ppm/C", Tolerance_%=5%, Value2=0.125W, Value_Code=470k
R2: library part CMP-0026866-2, "RES, 1.0, 5%, 0.063 W, 0402", Manufacturer=Vishay-Dale, Power_W=63mW, Supplier Part Number 1=541-1.0JCT-ND, TempCo="200 ppm/C", Tolerance_%=5%, Value2=0.063W, Value_Code=1R00, ValueDisplayed=1.0
R3: library part CMP-0018196-2, "RES, 30.0, 1%, 0.25 W, 1206", Manufacturer="Yageo America", Power_W=250mW, Supplier Part Number 1=311-30.0FRCT-ND, TempCo="100 ppm/C", Tolerance_%=1%, Value2=0.25W, Value_Code=30R0, ValueDisplayed=30.0
R4: library part CMP-0026926-1, "RES, 3.3, 5%, 0.063 W, 0402", Manufacturer=Vishay-Dale, Power_W=63mW, Supplier Part Number 1=541-3.3JCT-ND, TempCo="200 ppm/C", Tolerance_%=5%, Value2=0.063W, Value_Code=3R30, ValueDisplayed=3.3
R7: library part CMP-0026016-2, "RES, 14.3 k, 1%, 0.063 W, 0402", Manufacturer=Vishay-Dale, Power_W=63mW, Supplier Part Number 1=541-14.3KLCT-ND, TempCo="100 ppm/C", Tolerance_%=1%, Value2=0.063W, Value_Code=14k3, ValueDisplayed=14.3k
R8: library part CMP-0026315-1, "RES, 36.5 k, 1%, 0.063 W, 0402", Manufacturer=Vishay-Dale, Power_W=63mW, Supplier Part Number 1=541-36.5KLCT-ND, TempCo="100 ppm/C", Tolerance_%=1%, Value2=0.063W, Value_Code=36k5, ValueDisplayed=36.5k
R10: library part CMP-0026329-2, "RES, 3.01 k, 1%, 0.063 W, AEC-Q200 Grade 0, 0402", Manufacturer=Vishay-Dale, Power_W=63mW, Supplier Part Number 1=541-3.01KLCT-ND, TempCo="100 ppm/C", Tolerance_%=1%, Value2=0.063W, Value_Code=3k01, ValueDisplayed=3.01k
R11: library part CMP-0024175-2, "RES, 38.8 k, 0.1%, 0.1 W, 0603", Manufacturer="Yageo America", Power_W=100mW, TempCo="25 ppm/C", Tolerance_%=0.1%, Value2=0.1W, Value_Code=38k8, ValueDisplayed=38.8k
R12: library part CMP-0026133-1, "RES, 1.10, 1%, 0.063 W, 0402", Manufacturer=Vishay-Dale, Power_W=63mW, Supplier Part Number 1=541-1.10LLCT-ND, TempCo="100 ppm/C", Tolerance_%=1%, Value2=0.063W, Value_Code=1R10, ValueDisplayed=1.10
R13: library part CMP-0026022-3, "RES, 150, 1%, 0.063 W, AEC-Q200 Grade 0, 0402", Manufacturer=Vishay-Dale, Power_W=63mW, Supplier Part Number 1=541-150LCT-ND, TempCo="100 ppm/C", Tolerance_%=1%, Value2=0.063W, Value_Code=150R, ValueDisplayed=150
R14: library part CMP-0026027-3, "RES, 15.0 k, 1%, 0.063 W, AEC-Q200 Grade 0, 0402", Manufacturer=Vishay-Dale, Power_W=63mW, Supplier Part Number 1=541-15.0KLCT-ND, TempCo="100 ppm/C", Tolerance_%=1%, Value2=0.063W, Value_Code=15k0, ValueDisplayed=15.0k
R15: library part CMP-0026739-1, "RES, 4.70 k, 1%, 0.0625 W, 0402", Manufacturer="Yageo America", Power_W=62.5mW, Supplier Part Number 1=311-4.7KLRCT-ND, TempCo="100 ppm/C", Tolerance_%=1%, Value2=0.0625W, Value_Code=4k70, ValueDisplayed=4.70k
R19: library part CMP-0025686-1, "RES, 10.0 k, 0.1%, 0.1 W, AEC-Q200 Grade 1, 0603", Manufacturer=Vishay-Dale, Power_W=100mW, Supplier Part Number 1=TNP10.0KAACT-ND, TempCo="25 ppm/C", Tolerance_%=0.1%, Value2=0.1W, Value_Code=10k0, ValueDisplayed=10.0k
R20: library part CMP-0023186-5, "RES, 56.2 k, 1%, 0.1 W, 0603", Manufacturer=Yageo, Power_W=100mW, Supplier Part Number 1=311-56.2KHRCT-ND, TempCo="100 ppm/C", Tolerance_%=1%, Value2=0.1W, Value_Code=56k2, ValueDisplayed=56.2k
R32: library part CMP-0023013-5, "RES, 300, 1%, 0.1 W, 0603", Manufacturer=Yageo, Power_W=100mW, Supplier Part Number 1=311-300HRCT-ND, TempCo="100 ppm/C", Tolerance_%=1%, Value2=0.1W, Value_Code=300R, ValueDisplayed=300
R42: library part CMP-0026543-2, "RES, 75.0 k, 1%, 0.063 W, AEC-Q200 Grade 0, 0402", Manufacturer=Vishay-Dale, Power_W=63mW, Supplier Part Number 1=541-75.0KLCT-ND, TempCo="100 ppm/C", Tolerance_%=1%, Value2=0.063W, Value_Code=75k0, ValueDisplayed=75.0k
R43: library part CMP-0026464-2, "RES, 5.23 k, 1%, 0.063 W, AEC-Q200 Grade 0, 0402", Manufacturer=Vishay-Dale, Power_W=63mW, Supplier Part Number 1=541-5.23KLCT-ND, TempCo="100 ppm/C", Tolerance_%=1%, Value2=0.063W, Value_Code=5k23, ValueDisplayed=5.23k
RT1: library part CMP-0002353-2, "Thermistor NTC, 100k ohm, 1%, 0402", Manufacturer=MuRata, Power_W=100mW, Tolerance_%=1%
U1: library part CMP-0086802-1, "FAST TURN-OFF INTELLIGENT RECTIF", Manufacturer="Monolithic Power Systems"
U2: library part CMP-0066199-1, "2.5V Low Iq Adjustable Precision Shunt Regulator, DBZ0003A (SOT-23-3)", Alternate Manufacturer="Texas Instruments"
U3: library part CMP-0006160-3, "Optocoupler, 5 kV, 63-125% CTR, SMT", Manufacturer=Vishay-Semiconductor, Supplier Part Number 1=VOL618A-2TCT-ND, Voltage_Isolation_Vrms=5kV
U8: library part CMP-0121635-2, Manufacturer="Texas Instruments", Operating Temperature Range=to, PartNumber=UCG28824

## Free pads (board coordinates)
  round 1.3 hole 1: 12(-27.439,12.833) 12(-23.884,12.75)

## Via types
v1: diameter 0.61, hole 0.3, TopLayer to BottomLayer, tented both sides, 71 vias
v2: diameter 0.4, hole 0.3, TopLayer to BottomLayer, tented both sides, 19 vias
v3: diameter 0.5, hole 0.2, TopLayer to BottomLayer, tented both sides, 12 vias
v4: diameter 0.5, hole 0.3, Layer2 to Layer5, tented both sides, 8 vias
v5: diameter 0.508, hole 0.305, TopLayer to BottomLayer, 5 vias

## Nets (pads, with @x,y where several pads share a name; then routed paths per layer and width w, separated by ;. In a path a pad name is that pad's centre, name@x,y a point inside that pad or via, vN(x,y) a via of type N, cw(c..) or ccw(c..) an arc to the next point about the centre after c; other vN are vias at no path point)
+12V: C6.1 C7.1 C17.2 C18.1 CN1C.17 EC6.1 EC7.1 Q1.5 Q1.6 Q1.7 Q1.8 Q1.9 R10.2 R11.1 R32.1 | length 30.3
  TopLayer w0.25: v1(18.009,13.132) 18.009,13.158 18.351,13.5 C6.1@18.5,13.5
  TopLayer w0.505: v1(18.5,13.7) 18.5,13.728 18.448,13.781 CN1C.17@18.448,15.653 ; CN1C.17@18.2,15.9 CN1C.17@18.448,15.653 ; CN1C.17@18.2,15.9 CN1C.17@18.448,15.653 ; CN1C.17@18.2,15.9 CN1C.17@18.448,15.653 ; CN1C.17@18.2,15.9 CN1C.17@18.448,15.653 ; CN1C.17@18.2,15.9 CN1C.17@18.448,15.653 ; CN1C.17@18.2,15.9 CN1C.17@18.448,15.653 ; CN1C.17@18.2,15.9 CN1C.17@18.448,15.653 ; CN1C.17@18.2,15.9 CN1C.17@18.448,15.653 ; CN1C.17@18.2,15.9 CN1C.17@18.448,15.653 ; CN1C.17@18.2,15.9 CN1C.17@18.448,15.653
  Layer3 w0.505: EC6.1@16.49,-4.548 EC7.1@16.49,-2.715
  Layer2 w0.505: EC7.1@16.49,-2.715 EC7.1@16.838,-2.367 ; v1(18.009,13.132) 18.009,13.16 18.48,13.631 18.48,13.68 v1(18.5,13.7)
  BottomLayer w0.3: C18.1@12.685,-8.66 12.8,-8.66 12.84,-8.619 12.84,-8.505 13.276,-8.069 14.362,-8.069 14.952,-8.66 R10.2@15.066,-8.66 16.516,-8.66 16.701,-8.846 16.766,-8.91
  BottomLayer w0.505: C17.2@16.175,-7 C17.2@16.306,-7 ; C17.2@16.175,-7 16.177,-6.808 16.589,-6.396 16.856,-6.396 16.856,-5.545 16.49,-5.18 ; C17.2@16.306,-7.054 16.442,-7.191 16.766,-7.515 16.766,-8.66 16.766,-8.781 16.701,-8.846 ; EC7.1@16.49,-2.715 16.421,-2.646 16.421,-0.521 C7.1@16.352,-0.452 16.352,2.245 Q1.9@17.755,3.648 18.9,4.792 R32.1@18.9,7.199 R32.1@18.9,7.224 ; v1(18.009,13.132) 18.009,13.16 18.48,13.631 18.48,13.68 v1(18.5,13.7)
  other v1: 17.714,12.631 18.361,12.627 18.694,13.096 17.424,13.157 17.602,13.741
"+18V PVCC": C2.1 C4.1 CN1C.4 D1.1 | length 7.3
  BottomLayer w0.305: CN1C.4@-23.55,15.9 CN1C.4@-23.387,15.737
  BottomLayer w0.505: CN1C.4@-23.55,15.9 -23.302,14.753 -22.1,13.197 ; -22.099,13.196 ccw(c-21.7,13.506) -21.7,13.001 -21.359,13.001 v1(-21.018,12.914) -21.269,12.662 -21.269,10.504 D1.1@-21.427,10.346
+24V: C1.1 CN1C.9 D2.1 | length 7.3
  TopLayer w0.254: CN1C.9@10.2,15.9 10.2,15 11.5,13.7 13.061,13.7 13.645,13.116 13.645,12.67 14.415,11.9 14.462,11.9 14.793,11.569 D2.1@14.793,11.417
APGND: C16.2 NT1.2 R7.1 R8.1 R42.1 R43.1 RT1.1 U3.3 U8.10 | length 23.6
  Layer2 w0.2: v2(-23.012,-14.986) -23.825,-14.173 -23.825,-12.483 v2(-20.14,-8.798)
  BottomLayer w0.2: U8.10@-21.494,-6.595 -21.494,-7.252 -21.835,-7.593 -21.835,-8.417 -22.176,-8.758 NT1.2@-23.038,-8.758 -23.027,-8.769 R8.1@-20.14,-8.769 ; v2(-20.14,-8.798) -19.995,-8.798 -19.922,-8.871 -19.922,-9.016 -19.769,-9.169 -18.561,-9.169 -18.22,-8.829 R42.1@-18.22,-6.645 RT1.1@-18.22,-3.544
  BottomLayer w0.3: v2@-22.985,-14.986 -21.334,-14.986 U3.3@-21.25,-15.07
HVC: C5.1 D9.1 R4.1 | length 4.2
  BottomLayer w0.254: R4.1@12.979,9.978 13.082,9.978 13.146,10.041 13.146,10.66 13.545,11.059 13.545,12.2 13.862,12.517 14.507,12.517 14.838,12.847 D9.1@14.838,13
NetC3_1: C3.1 R1.1 R3.2 | length 8.1
  TopLayer w0.305: R1.1@-25.349,10.287 -25.492,10.144 -25.492,9.056 -25.109,8.673 -24.778,8.673 -24.28,8.175 C3.1@-24.28,8.164 -24.557,7.887 -24.557,6.342 -24.403,6.342 -24.295,6.234 -24.295,5.501 -24.244,5.451 -24.244,5 -23.747,4.502 -23.747,3.607 R3.2@-23.848,3.505
NetC15_1: C15.1 U8.11 | length 1.4
  BottomLayer w0.2: C15.1@-22.493,-7.688 -22.493,-7.497 -22.339,-7.343 -22.222,-7.343 -21.994,-7.116 U8.11@-21.994,-6.595
NetC16_1: C16.1 R12.1 U8.5 | length 5.3
  Layer2 w0.2: v2(-19.379,-4.728) -18.598,-4.728 -18.11,-5.215 -18.11,-6.649 v2(-18.936,-7.475)
  BottomLayer w0.2: U8.5@-20.344,-4.97 -20.319,-4.945 -19.781,-4.945 -19.584,-4.747 -19.242,-4.747 C16.1@-19.21,-4.716
NetC18_2: C18.2 R13.2 | length 1.2
  BottomLayer w0.3: C18.2@12.685,-9.676 R13.2@13.862,-9.676
NetC20_1: C20.1 R15.1 | length 0.7
  BottomLayer w0.3: R15.1@17.103,-13.773 C20.1@17.103,-13.081
NetC20_2: C20.2 C21.2 R14.1 U2.1 U3.2 | length 31.9
  Layer4 w0.3: v2(13.119,-12.47) 16.184,-12.47 16.599,-12.056 v2(16.626,-12.056)
  BottomLayer w0.3: U3.2@-11.75,-15.07 -11.465,-15.355 R14.1@11.762,-15.355 12.116,-15.355 13.146,-14.324 U2.1@13.146,-12.5 ; C21.2@16.144,-12.084 16.154,-12.074 17.094,-12.074 C20.2@17.103,-12.065
NetC21_1: C21.1 R11.2 R15.2 R19.2 U2.2 | length 9.6
  BottomLayer w0.3: C21.1@16.144,-13.1 16.104,-13.059 15.405,-13.059 U2.2@15.196,-12.85 ; 16.775,-10.502 15.897,-10.502 15.046,-11.353 U2.2@15.046,-12.5 15.046,-12.7 U2.2@15.196,-12.85 ; R15.2@17.103,-14.789 16.208,-14.789 15.196,-13.777 U2.2@15.196,-12.85
  BottomLayer w0.5: 16.775,-10.502 18.42,-10.502 R19.2@18.428,-10.494
NetC31_1: C31.1 U1.4 | length 1.5
  BottomLayer w0.254: U1.4@17,9.47 17,10.151 17.222,10.373 17.335,10.373 17.462,10.5 C31.1@17.462,10.69
NetC32_1: C32.1 R4.2 U1.1 | length 3.4
  TopLayer w0.25: v2(12.711,8.539) 12.739,8.511 12.739,7.955 C32.1@12.834,7.861 12.834,7.715 13.012,7.537 v2(13.36,7.188)
  BottomLayer w0.25: v2(12.711,8.539) 12.711,8.58 12.8,8.669 12.8,8.896 12.865,8.962 R4.2@12.979,8.962
  BottomLayer w0.3: v2(13.36,7.188) 13.387,7.188 13.619,7.42 14.25,7.42 U1.1@14.4,7.57
NetD1_2: D1.2 | length 3.9
  Layer3 w0.5: -18.12,7.087 -18.11,7.097 v1(-18.11,8.8)
  BottomLayer w0.4: v1(-18.12,8.154) -18.115,8.159 -18.115,8.795 v1(-18.11,8.8)
  BottomLayer w0.505: D1.2@-18.152,10.346 -18.13,10.324 -18.13,8.82 v1(-18.11,8.8)
NetD3_1: D3.1 R3.1 | length 5.7
  TopLayer w0.305: -27.45,3.997 -27.45,4.043 -27.246,4.043 -26.748,3.545 R3.1@-26.748,3.505 ; D3.1@-26.8,0.1 -27.126,0.426 -27.126,1.712 -27.06,1.778 -27.06,3.194 R3.1@-26.748,3.505 ; -26.647,4.502 -26.647,3.607 R3.1@-26.748,3.505
NetQ1_4: Q1.4 U1.5 | length 4.1
  Layer3 w0.5: v2(14.255,5.553) 17,8.297 v2(17,8.52)
NetR2_1: R2.1 U8.1 | length 10.9
  Layer3 w0.25: v1(-26.467,6.426) -26.416,6.375 -26.416,-0.731 v1(-25.394,-1.753)
  BottomLayer w0.25: R2.1@-27.889,6.934 -26.975,6.934 v1(-26.467,6.426)
  BottomLayer w0.254: v1(-25.394,-1.753) -25.373,-1.774 -24.741,-1.774 U8.1@-24.719,-1.795
NetR7_2: R7.2 U8.9 | length 1.2
  BottomLayer w0.2: R7.2@-21.016,-7.764 -21.016,-6.617 U8.9@-20.994,-6.595
NetR8_2: R8.2 U8.8 | length 1.4
  BottomLayer w0.2: U8.8@-20.457,-6.483 -20.127,-6.813 R8.2@-20.127,-7.764
NetR10_1: R10.1 R13.1 R14.2 U3.1 | length 33.3
  BottomLayer w0.3: U3.1@-11.75,-12.53 -11.532,-12.748 -11.532,-13.577 -10.304,-14.805 11.181,-14.805 11.647,-14.339 R14.2@11.762,-14.339 ; 11.762,-14.147 11.762,-12.5 11.762,-11.678 13.099,-10.34 14.288,-10.34 R10.1@14.952,-9.676 ; R13.1@13.862,-8.66 13.976,-8.66 14.017,-8.7 14.017,-8.74 R10.1@14.952,-9.676 ; R10.1@15.066,-9.676 R10.1@14.952,-9.676
NetR12_2: R12.2 U3.4 | length 7.2
  Layer2 w0.2: v2(-22.885,-12.344) -19.112,-8.571 -18.999,-8.571 v2(-18.961,-8.532)
  BottomLayer w0.3: v2@-22.858,-12.344 -21.436,-12.344 U3.4@-21.25,-12.53
NetR20_2: R20.2 U1.3 | length 0.5
  BottomLayer w0.254: U1.3@14.4,9.47 14.507,9.577 v2(14.507,9.964)
NetR32_2: R32.2 U1.6 | length 2.4
  BottomLayer w0.3: U1.6@17,7.57 17.15,7.72 17.845,7.72 18.9,8.774 R32.2@18.9,8.799
NetR42_2: R42.2 U8.7 | length 1.5
  BottomLayer w0.2: U8.7@-20.344,-5.97 -20.319,-5.995 -19.832,-5.995 -19.387,-6.441 -19.327,-6.441 -19.236,-6.531 R42.2@-19.236,-6.645
NetR43_2: R43.2 U8.6 | length 1.2
  BottomLayer w0.2: U8.6@-20.344,-5.47 -20.319,-5.495 -19.301,-5.495 -19.21,-5.586 R43.2@-19.21,-5.627
NetRT1_2: RT1.2 U8.4 | length 1.7
  BottomLayer w0.2: U8.4@-20.344,-4.47 -20.319,-4.445 -20.065,-4.445 -19.929,-4.445 -19.694,-4.211 -19.694,-4.002 -19.441,-3.748 -19.327,-3.748 -19.236,-3.658 RT1.2@-19.236,-3.544
PGND: C2.2 C4.2 C11.2 C15.2 C19.2 C22.2 CN1C.3 CY2.2 NT1.1 pad.12@-23.884,12.75 U8.3 U8.12 | length 20.9
  TopLayer w0.5: v1(-23.625,12.5) -22.235,11.11 -20.121,11.11 -19.257,11.974 -19.257,12.361 -18.78,12.838 v1(-18.778,12.838)
  BottomLayer w0.3: -23.884,-8.625 -24.017,-8.492 C15.2@-24.017,-7.688 -23.913,-7.584 -23.913,-5.515 U8.12@-23.793,-5.394 ; -20.938,-3.745 -20.738,-3.945 U8.3@-20.344,-3.945
  BottomLayer w0.305: v1(-24.74,13.056) -24.644,13.056 -24.529,12.941 -24.344,12.941 -23.938,12.535 -23.938,12.5 C22.2@-24.192,12.246 ; C22.2@-23.887,12.5 v1(-23.625,12.5) -23.612,12.512 -23.612,13.188 v1(-23.6,13.2)
  BottomLayer w0.5: v1@-26.2,-4.949 -25.805,-5.344 -25.32,-5.344 U8.12@-25.005,-5.66 ; v1(-24.74,13.056) -24.71,13.056 -24.513,12.859 -24.5,12.859 -24.5,12.546 C22.2@-24.2,12.246 ; C19.2@-22.967,2.535 C19.2@-22.967,2.785 ; v1@-19.753,8.543 -19.753,11.142 -19.217,11.677 -19.217,12.627 C2.2@-18.945,12.9 ; v1(-19.66,7.887) v1(-19.66,8.52)
  other v1: -26.116,-9.91 -25.187,-9.927 -27.253,-9.851 -25.187,-9.182 -26.116,-9.165 -27.253,-9.106 -25.206,-8.292 -26.135,-8.276 -27.272,-8.216 -26.155,-7.497 -25.226,-7.514 -27.292,-7.438 -26.155,-6.385 -25.256,-6.385 -27.308,-6.349 -26.155,-5.64 -25.256,-5.64 -27.308,-5.604 -26.174,-4.751 -25.275,-4.751 -27.327,-4.715 -26.193,-3.972 -25.294,-3.972 -27.346,-3.936 -24.561,12.303 -24.243,13.664
  other v3: -24.394,-5.795 -23.404,-5.795 -22.134,-5.795 -21.144,-5.795 -24.394,-4.92 -23.404,-4.92 -22.134,-4.92 -21.144,-4.92 -24.394,-4.045 -23.404,-4.045 -22.134,-4.045 -21.144,-4.045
